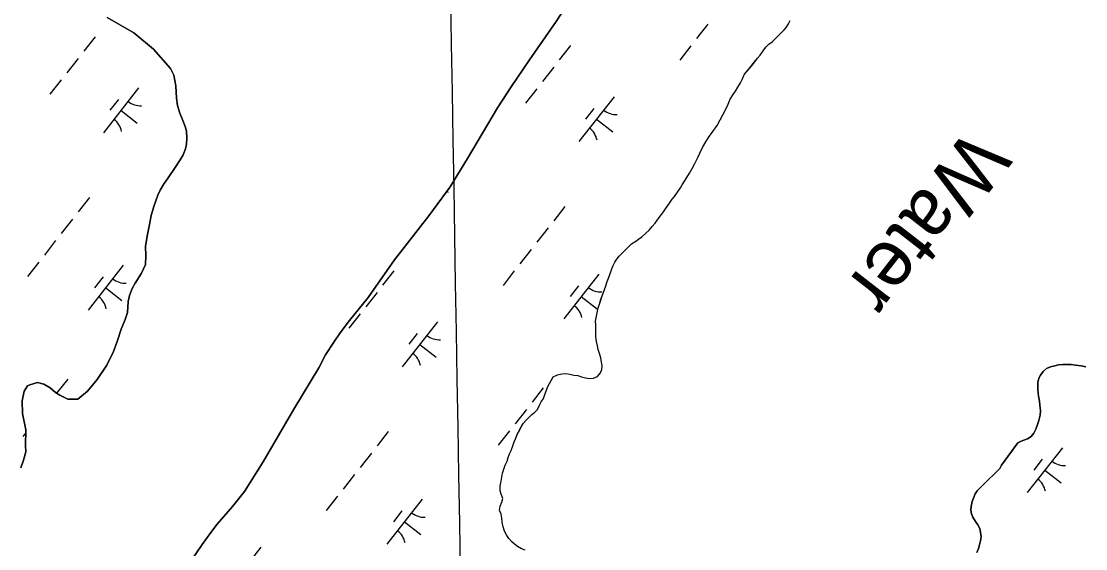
# Model space of a CAD drawing. Extents: x 3896831 to 3918110, y 171006 to 193349.
# Drawn here: x 3909330 to 3910262, y 178046 to 178509 of the extents above; entities that cross this region are included whole.
import ezdxf

# ---------------------------------------------------------------- set-up
doc = ezdxf.new("R2010")
doc.units = 0
for name, color, linetype in [('V-GRID-MAJR', 7, 'Continuous'), ('V-RIVR-IDEN', 7, 'Continuous'), ('V-TOPO-SHOR', 7, 'Continuous'), ('V-WETL-SWMP', 7, 'Continuous')]:
    doc.layers.add(name, color=color, linetype=linetype)

msp = doc.modelspace()

# ---------------------------------------------------------------- linework, layer by layer
at = {"layer": 'V-GRID-MAJR'}
msp.add_spline([(3909752.76, 175802.03), (3909660.52, 181175.42), (3909556.5, 187235.56), (3909500.71, 190486.24)], degree=3, dxfattribs=at)
at = {"layer": 'V-TOPO-SHOR'}
for points in [[(3909488.26, 178050.08), (3909495.83, 178060.47), (3909501.33, 178067.84), (3909514.75, 178083.45), (3909525.17, 178096.46), (3909541.48, 178122.43), (3909568.51, 178168.75), (3909590.25, 178205.02), (3909596.09, 178216.39), (3909603.41, 178227.46), (3909608.93, 178235.75), (3909617.17, 178246.4), (3909633.49, 178266.63), (3909656.76, 178299.8), (3909686.69, 178338.18), (3909705.53, 178363.69), (3909720.48, 178388.62), (3909746.94, 178433.08), (3909758.81, 178451.4), (3909774.94, 178475.11), (3909798.36, 178508.68), (3909820.87, 178543.87)], [(3909424.36, 178268.46), (3909426.89, 178274.41), (3909429.39, 178279.3), (3909435.04, 178287.85), (3909438.4, 178295.52), (3909438.83, 178303.24), (3909438.61, 178311.65), (3909440.3, 178322.02), (3909442.24, 178331.99), (3909443.45, 178338.63), (3909445.75, 178346.46), (3909449.43, 178356.38), (3909451.25, 178360.75), (3909454.16, 178365.62), (3909458.42, 178371.54), (3909464.48, 178380.75), (3909469.02, 178387.32), (3909471.65, 178391.67), (3909473.63, 178396.97), (3909474.39, 178401.22), (3909474.76, 178406.41), (3909474.49, 178412.42), (3909473.38, 178416.71), (3909471.35, 178421.83), (3909468.55, 178428.29), (3909466.56, 178435.14), (3909465.63, 178441.56), (3909465.06, 178452.24), (3909463.25, 178461.75), (3909460.31, 178467.55), (3909445.59, 178484.54), (3909428.28, 178498.65), (3909404.95, 178512.21)], [(3909887.17, 178334.86), (3909889.5, 178338.01), (3909891.7, 178341.04), (3909894.04, 178344.45), (3909896.93, 178348.52), (3909899.95, 178352.86), (3909901.87, 178355.35), (3909904.62, 178359.16), (3909907.09, 178362.71), (3909908.75, 178365.47), (3909910.69, 178368.77), (3909912.89, 178371.92), (3909915.23, 178375.74), (3909917.58, 178379.82), (3909919.67, 178384.04), (3909922.32, 178389.45), (3909924.27, 178393.28), (3909926.64, 178398.3), (3909929.41, 178403.17), (3909931.89, 178406.85), (3909939.31, 178417.36), (3909946.95, 178431.73), (3909948.91, 178436.23), (3909950.87, 178440.58), (3909953.35, 178444.53), (3909955.28, 178447.56), (3909957.48, 178450.98), (3909959.7, 178454.93), (3909961.36, 178457.83), (3909963.2, 178462.59), (3909966.48, 178466.39), (3909969.34, 178469.66), (3909972.22, 178473.2), (3909974.82, 178476.48), (3909977.01, 178479.23), (3909980.31, 178483.96), (3909982.37, 178486.59), (3909984.55, 178488.81), (3909987.52, 178490.74), (3909990.25, 178493.49), (3909992.83, 178496.1), (3909995.43, 178498.84), (3909998.01, 178501.45), (3910000.06, 178503.68), (3910001.99, 178506.57), (3910003.38, 178509.47)], [(3909764.46, 178048.26), (3909761.71, 178050.32), (3909759.35, 178052.37), (3909756.75, 178055.35), (3909754.94, 178058.06), (3909753.15, 178061.83), (3909751.89, 178065.46), (3909751.05, 178069.61), (3909750.72, 178073.08), (3909750, 178076.7), (3909748.74, 178080.19), (3909749.34, 178083.51), (3909750.75, 178087.21), (3909751.49, 178090.4), (3909750.23, 178094.29), (3909749.36, 178097.24), (3909749.31, 178101.11), (3909750.08, 178105.63), (3909750.68, 178109.08), (3909751.42, 178112.66), (3909752.56, 178116.24), (3909753.7, 178119.55), (3909755.24, 178122.98), (3909756.25, 178126.43), (3909757.51, 178129.6), (3909758.77, 178132.51), (3909760.33, 178136.61), (3909761.6, 178140.05), (3909762.87, 178143.36), (3909764.27, 178146.53), (3909766.08, 178149.95), (3909767.74, 178153.12), (3909769.81, 178156.41), (3909772, 178159.03), (3909774.59, 178161.77), (3909776.9, 178163.99), (3909779.48, 178166.07), (3909781.8, 178168.56), (3909783.74, 178172.12), (3909785.14, 178175.02), (3909787.07, 178178.18), (3909788.47, 178181.48), (3909789.89, 178185.32), (3909790.89, 178188.5), (3909792.41, 178191.13), (3909793.93, 178193.77), (3909795.73, 178196.93), (3909799.51, 178198.85), (3909803.12, 178199.57), (3909806.46, 178200.04), (3909810.31, 178199.29), (3909813.9, 178198.55), (3909817.36, 178198.21), (3909820.4, 178197.21), (3909823.98, 178196.07), (3909827.57, 178195.73), (3909831.04, 178195.92), (3909834.54, 178197.31), (3909837, 178200.46), (3909838.27, 178203.36), (3909838.47, 178206.83), (3909838.14, 178209.9), (3909837.42, 178213.78), (3909836.17, 178217.54), (3909835.04, 178221.03), (3909834.44, 178224.24), (3909833.72, 178227.99), (3909833.14, 178232.01), (3909832.94, 178235.48), (3909833.01, 178238.54), (3909832.96, 178242.54), (3909832.9, 178246.01), (3909833.52, 178250.13), (3909834.12, 178253.18), (3909835.15, 178257.7), (3909836.14, 178260.74), (3909837.29, 178264.32), (3909838.42, 178267.36), (3909839.55, 178270.4), (3909840.68, 178273.58), (3909841.81, 178276.89), (3909843.09, 178280.59), (3909844.09, 178283.51), (3909845.36, 178286.95), (3909846.36, 178290.12), (3909848.04, 178294.09), (3909849.59, 178297.66), (3909851.38, 178300.29), (3909853.56, 178302.77), (3909856.15, 178305.52), (3909858.47, 178308), (3909861.47, 178310.87), (3909864.32, 178313.61), (3909867.97, 178315.93), (3909870.41, 178317.75), (3909873.26, 178319.96), (3909876.79, 178323.08), (3909879.77, 178325.55), (3909882.38, 178328.83), (3909884.97, 178331.71), (3909887.17, 178334.86)], [(3909329.38, 178117.18), (3909331.53, 178124.07), (3909333.55, 178131.23), (3909333.39, 178136.57), (3909333.56, 178150.58), (3909330.79, 178164.77), (3909330.49, 178176.12), (3909332.13, 178184.36), (3909335.04, 178189.23), (3909337.19, 178190.12), (3909343.77, 178191.98), (3909349.47, 178190.53), (3909355.01, 178187.34), (3909359.59, 178183.24), (3909363.55, 178180.89), (3909370.41, 178177.41), (3909379.09, 178177.63), (3909387.64, 178184.52), (3909396.26, 178194.75), (3909404.53, 178207.38), (3909410.38, 178219.4), (3909413.64, 178228.13), (3909417.07, 178239), (3909420.72, 178247.46), (3909422.84, 178253.42), (3909423.31, 178263.01), (3909424.36, 178268.46)], [(3910221.13, 178196.03), (3910222.7, 178198.66), (3910225.06, 178201.73), (3910227.95, 178204.42), (3910231.44, 178205.95), (3910235.06, 178206.86), (3910238.41, 178207.45), (3910242.15, 178207.77), (3910245.48, 178207.84), (3910249.35, 178207.89), (3910253.34, 178207.4), (3910258.13, 178206.64), (3910262.38, 178205.88)], [(3910166.89, 178043.04), (3910168.29, 178046.48), (3910169.3, 178049.79), (3910170.04, 178053.37), (3910170.51, 178056.83), (3910170.2, 178060.7), (3910169.33, 178063.92), (3910167.8, 178067.18), (3910165.57, 178070.32), (3910163.28, 178074.13), (3910162.19, 178077.06), (3910161.49, 178080.22), (3910161.77, 178083.47), (3910162.74, 178087.79), (3910163.92, 178090.6), (3910165.47, 178094.43), (3910167.12, 178097.06), (3910169.98, 178100.07), (3910173.66, 178103.59), (3910175.97, 178105.81), (3910178.02, 178108.03), (3910181.01, 178110.9), (3910184.14, 178113.77), (3910186.87, 178116.78), (3910188.53, 178119.68), (3910202.68, 178139.11), (3910205.77, 178140.51), (3910211.15, 178142.67), (3910214.4, 178144.86), (3910216.72, 178147.75), (3910218.53, 178151.04), (3910219.8, 178154.48), (3910221.23, 178158.86), (3910222.25, 178163.37), (3910222.48, 178167.63), (3910222.18, 178172.33), (3910221.63, 178175.73), (3910220.82, 178180.22), (3910220.17, 178186.02), (3910220.25, 178192.18), (3910221.13, 178196.03)], [(3909319.59, 177836.97), (3909330.11, 177847.7), (3909339.77, 177856.31), (3909347.55, 177864.16), (3909357.1, 177873.31), (3909362.55, 177878.67), (3909370.07, 177886.67), (3909376.38, 177894.68), (3909381.91, 177903.65), (3909387.01, 177910.75), (3909427.16, 177964.94), (3909463.83, 178012.93), (3909478.33, 178035.46), (3909488.26, 178050.08)], [(3909771.06, 178044.92), (3909768.02, 178046.32), (3909764.46, 178048.26)]]:
    msp.add_lwpolyline(points, dxfattribs=at)
at = {"layer": 'V-WETL-SWMP'}
for p, q in [((3909820.87, 178543.87), (3909798.36, 178508.68)), ((3909404.95, 178512.21), (3909428.28, 178498.65)), ((3909798.36, 178508.68), (3909774.94, 178475.11)), ((3910001.99, 178506.57), (3910003.38, 178509.47)), ((3909428.28, 178498.65), (3909445.59, 178484.54)), ((3909931.2, 178506.31), (3909921.33, 178493.72)), ((3909992.83, 178496.1), (3909995.43, 178498.84)), ((3909995.43, 178498.84), (3909998.01, 178501.46)), ((3909998.01, 178501.46), (3910000.06, 178503.68)), ((3910000.06, 178503.68), (3910001.99, 178506.57)), ((3909394.29, 178495.25), (3909384.42, 178482.66)), ((3909982.37, 178486.58), (3909984.55, 178488.81)), ((3909984.55, 178488.81), (3909987.52, 178490.74)), ((3909987.52, 178490.74), (3909990.25, 178493.48)), ((3909990.25, 178493.48), (3909992.83, 178496.1)), ((3909445.59, 178484.54), (3909460.31, 178467.55)), ((3909810.94, 178487.55), (3909801.07, 178474.96)), ((3909916.4, 178487.42), (3909906.53, 178474.83)), ((3909977.01, 178479.23), (3909980.31, 178483.96)), ((3909980.31, 178483.96), (3909982.37, 178486.58)), ((3909379.49, 178476.36), (3909369.62, 178463.77)), ((3909774.94, 178475.11), (3909758.81, 178451.4)), ((3909972.74, 178474.49), (3909965.52, 178465.29)), ((3909969.34, 178469.66), (3909972.22, 178473.2)), ((3909972.22, 178473.2), (3909974.82, 178476.48)), ((3909974.82, 178476.48), (3909977.01, 178479.23)), ((3909460.31, 178467.55), (3909463.25, 178461.75)), ((3909463.25, 178461.75), (3909465.06, 178452.24)), ((3909796.13, 178468.66), (3909786.26, 178456.07)), ((3909961.36, 178457.83), (3909963.2, 178462.59)), ((3909963.2, 178462.59), (3909966.48, 178466.39)), ((3909966.48, 178466.39), (3909969.34, 178469.66)), ((3909364.68, 178457.48), (3909354.81, 178444.88)), ((3909465.06, 178452.24), (3909465.63, 178441.56)), ((3909758.81, 178451.4), (3909746.94, 178433.08)), ((3909957.48, 178450.98), (3909959.7, 178454.93)), ((3909959.7, 178454.93), (3909961.36, 178457.83)), ((3909432.5, 178450.44), (3909401.66, 178411.09)), ((3909781.33, 178449.78), (3909771.46, 178437.18)), ((3909849.14, 178442.74), (3909818.3, 178403.39)), ((3909950.86, 178440.58), (3909953.35, 178444.53)), ((3909953.35, 178444.53), (3909955.28, 178447.56)), ((3909955.28, 178447.56), (3909957.48, 178450.98)), ((3909414.71, 178440.24), (3909407.3, 178430.8)), ((3909465.63, 178441.56), (3909466.56, 178435.14)), ((3909466.56, 178435.14), (3909468.55, 178428.29)), ((3909746.94, 178433.08), (3909720.48, 178388.62)), ((3909946.95, 178431.73), (3909948.91, 178436.23)), ((3909948.91, 178436.23), (3909950.86, 178440.58)), ((3909417.08, 178430.76), (3909431.25, 178419.66)), ((3909468.55, 178428.29), (3909471.35, 178421.83)), ((3909831.35, 178432.54), (3909823.95, 178423.1)), ((3909939.31, 178417.36), (3909946.95, 178431.73)), ((3909471.35, 178421.83), (3909473.38, 178416.71)), ((3909473.38, 178416.71), (3909474.49, 178412.42)), ((3909833.72, 178423.06), (3909847.89, 178411.96)), ((3909931.89, 178406.85), (3909939.31, 178417.36)), ((3909474.76, 178406.41), (3909474.39, 178401.22)), ((3909474.49, 178412.42), (3909474.76, 178406.41)), ((3909929.41, 178403.17), (3909931.89, 178406.85)), ((3909473.63, 178396.96), (3909471.65, 178391.67)), ((3909474.39, 178401.22), (3909473.63, 178396.96)), ((3909924.27, 178393.28), (3909926.64, 178398.3)), ((3909926.64, 178398.3), (3909929.41, 178403.17)), ((3909469.02, 178387.32), (3909464.48, 178380.75)), ((3909471.65, 178391.67), (3909469.02, 178387.32)), ((3909720.48, 178388.62), (3909705.53, 178363.69)), ((3909919.67, 178384.04), (3909922.32, 178389.45)), ((3909922.32, 178389.45), (3909924.27, 178393.28)), ((3909464.48, 178380.75), (3909458.42, 178371.54)), ((3909915.23, 178375.74), (3909917.58, 178379.82)), ((3909917.58, 178379.82), (3909919.67, 178384.04)), ((3909458.42, 178371.54), (3909454.16, 178365.62)), ((3909908.75, 178365.47), (3909910.69, 178368.77)), ((3909910.69, 178368.77), (3909912.88, 178371.92)), ((3909912.88, 178371.92), (3909915.23, 178375.74)), ((3909451.25, 178360.75), (3909449.43, 178356.39)), ((3909454.16, 178365.62), (3909451.25, 178360.75)), ((3909705.53, 178363.69), (3909686.69, 178338.18)), ((3909702.61, 178359.74), (3909703.55, 178359)), ((3909901.87, 178355.35), (3909904.62, 178359.16)), ((3909904.62, 178359.16), (3909907.09, 178362.71)), ((3909907.09, 178362.71), (3909908.75, 178365.47)), ((3909389.37, 178354.28), (3909379.5, 178341.68)), ((3909449.43, 178356.39), (3909445.75, 178346.46)), ((3909896.93, 178348.52), (3909899.95, 178352.86)), ((3909899.95, 178352.86), (3909901.87, 178355.35)), ((3909445.75, 178346.46), (3909443.45, 178338.63)), ((3909806.01, 178346.58), (3909796.14, 178333.98)), ((3909889.5, 178338.01), (3909891.7, 178341.03)), ((3909891.7, 178341.03), (3909894.04, 178344.45)), ((3909894.04, 178344.45), (3909896.93, 178348.52)), ((3909374.56, 178335.39), (3909364.69, 178322.79)), ((3909442.24, 178331.99), (3909440.3, 178322.02)), ((3909443.45, 178338.63), (3909442.24, 178331.99)), ((3909686.69, 178338.18), (3909656.76, 178299.8)), ((3909882.38, 178328.83), (3909884.97, 178331.71)), ((3909884.97, 178331.71), (3909887.17, 178334.86)), ((3909887.17, 178334.86), (3909889.5, 178338.01)), ((3909440.3, 178322.02), (3909438.61, 178311.65)), ((3909791.2, 178327.69), (3909781.33, 178315.09)), ((3909873.26, 178319.96), (3909876.79, 178323.08)), ((3909876.79, 178323.08), (3909879.77, 178325.55)), ((3909879.77, 178325.55), (3909882.38, 178328.83)), ((3909359.76, 178316.5), (3909349.89, 178303.9)), ((3909438.61, 178311.65), (3909438.83, 178303.24)), ((3909858.47, 178308), (3909864.32, 178313.61)), ((3909864.32, 178313.61), (3909867.97, 178315.93)), ((3909867.97, 178315.93), (3909870.41, 178317.75)), ((3909870.41, 178317.75), (3909873.26, 178319.96)), ((3909438.83, 178303.24), (3909438.4, 178295.51)), ((3909776.4, 178308.8), (3909766.53, 178296.2)), ((3909851.38, 178300.29), (3909853.56, 178302.77)), ((3909853.56, 178302.77), (3909856.15, 178305.52)), ((3909856.15, 178305.52), (3909858.47, 178308)), ((3909344.95, 178297.61), (3909335.08, 178285.01)), ((3909419.08, 178294.87), (3909388.24, 178255.52)), ((3909438.4, 178295.51), (3909435.04, 178287.85)), ((3909656.76, 178299.8), (3909633.49, 178266.63)), ((3909846.36, 178290.12), (3909848.04, 178294.09)), ((3909848.04, 178294.09), (3909849.59, 178297.66)), ((3909849.59, 178297.66), (3909851.38, 178300.29)), ((3909401.29, 178284.68), (3909393.89, 178275.23)), ((3909435.04, 178287.85), (3909429.39, 178279.3)), ((3909656.13, 178290.04), (3909646.26, 178277.44)), ((3909761.59, 178289.91), (3909751.72, 178277.31)), ((3909835.73, 178287.17), (3909804.88, 178247.82)), ((3909844.09, 178283.51), (3909845.36, 178286.95)), ((3909845.36, 178286.95), (3909846.36, 178290.12)), ((3909403.66, 178275.19), (3909417.83, 178264.09)), ((3909426.89, 178274.41), (3909424.36, 178268.46)), ((3909429.39, 178279.3), (3909426.89, 178274.41)), ((3909817.93, 178276.98), (3909810.53, 178267.53)), ((3909840.68, 178273.58), (3909841.82, 178276.89)), ((3909841.82, 178276.89), (3909843.09, 178280.59)), ((3909843.09, 178280.59), (3909844.09, 178283.51)), ((3909424.36, 178268.46), (3909423.31, 178263.01)), ((3909633.49, 178266.63), (3909617.17, 178246.4)), ((3909641.33, 178271.15), (3909631.46, 178258.55)), ((3909820.31, 178267.49), (3909834.47, 178256.39)), ((3909837.28, 178264.32), (3909839.55, 178270.4)), ((3909839.55, 178270.4), (3909840.68, 178273.58)), ((3909423.31, 178263.01), (3909422.84, 178253.42)), ((3909834.12, 178253.18), (3909835.15, 178257.7)), ((3909835.15, 178257.7), (3909836.14, 178260.74)), ((3909836.14, 178260.74), (3909837.28, 178264.32)), ((3909420.71, 178247.46), (3909417.07, 178239)), ((3909422.84, 178253.42), (3909420.71, 178247.46)), ((3909617.17, 178246.4), (3909608.93, 178235.75)), ((3909626.52, 178252.26), (3909616.65, 178239.67)), ((3909832.9, 178246.01), (3909833.52, 178250.13)), ((3909833.52, 178250.13), (3909834.12, 178253.18)), ((3909417.07, 178239), (3909413.64, 178228.13)), ((3909694.34, 178245.22), (3909663.49, 178205.87)), ((3909832.96, 178242.54), (3909832.9, 178246.01)), ((3909832.94, 178235.48), (3909833.01, 178238.54)), ((3909833.01, 178238.54), (3909832.96, 178242.54)), ((3909413.64, 178228.13), (3909410.38, 178219.39)), ((3909608.93, 178235.75), (3909603.41, 178227.46)), ((3909676.54, 178235.03), (3909669.14, 178225.58)), ((3909833.14, 178232.01), (3909832.94, 178235.48)), ((3909833.72, 178227.99), (3909833.14, 178232.01)), ((3909834.44, 178224.24), (3909833.72, 178227.99)), ((3909410.38, 178219.39), (3909404.53, 178207.38)), ((3909603.41, 178227.46), (3909596.09, 178216.39)), ((3909678.92, 178225.55), (3909693.08, 178214.44)), ((3909835.04, 178221.03), (3909834.44, 178224.24)), ((3909836.17, 178217.54), (3909835.04, 178221.03)), ((3909596.09, 178216.39), (3909590.24, 178205.02)), ((3909837.42, 178213.78), (3909836.17, 178217.54)), ((3909838.14, 178209.9), (3909837.42, 178213.78)), ((3909838.47, 178206.83), (3909838.14, 178209.9)), ((3909404.53, 178207.38), (3909396.26, 178194.74)), ((3909590.24, 178205.02), (3909568.51, 178168.75)), ((3909803.12, 178199.57), (3909806.46, 178200.03)), ((3909806.46, 178200.03), (3909810.31, 178199.29)), ((3909834.54, 178197.31), (3909837, 178200.46)), ((3909837, 178200.46), (3909838.27, 178203.36)), ((3909838.27, 178203.36), (3909838.47, 178206.83)), ((3910225.06, 178201.73), (3910222.7, 178198.66)), ((3910227.95, 178204.42), (3910225.06, 178201.73)), ((3910231.44, 178205.95), (3910227.95, 178204.42)), ((3910235.06, 178206.86), (3910231.44, 178205.95)), ((3910238.41, 178207.45), (3910235.06, 178206.86)), ((3910242.15, 178207.77), (3910238.41, 178207.45)), ((3910245.48, 178207.84), (3910242.15, 178207.77)), ((3910249.35, 178207.89), (3910245.48, 178207.84)), ((3910253.34, 178207.4), (3910249.35, 178207.89)), ((3910258.13, 178206.64), (3910253.34, 178207.4)), ((3910262.38, 178205.88), (3910258.13, 178206.64)), ((3909343.77, 178191.98), (3909337.19, 178190.12)), ((3909349.47, 178190.53), (3909343.77, 178191.98)), ((3909355.01, 178187.34), (3909349.47, 178190.53)), ((3909370.41, 178195.13), (3909360.62, 178182.64)), ((3909396.26, 178194.74), (3909387.64, 178184.52)), ((3909790.89, 178188.5), (3909793.93, 178193.77)), ((3909793.93, 178193.77), (3909795.73, 178196.93)), ((3909795.73, 178196.93), (3909799.5, 178198.85)), ((3909799.5, 178198.85), (3909803.12, 178199.57)), ((3909810.31, 178199.29), (3909813.9, 178198.55)), ((3909813.9, 178198.55), (3909817.36, 178198.21)), ((3909817.36, 178198.21), (3909820.4, 178197.21)), ((3909820.4, 178197.21), (3909823.98, 178196.07)), ((3909823.98, 178196.07), (3909827.57, 178195.72)), ((3909827.57, 178195.72), (3909831.04, 178195.92)), ((3909831.04, 178195.92), (3909834.54, 178197.31)), ((3910220.25, 178192.18), (3910220.17, 178186.02)), ((3910221.13, 178196.03), (3910220.25, 178192.18)), ((3910222.7, 178198.66), (3910221.13, 178196.03)), ((3909332.13, 178184.36), (3909330.49, 178176.12)), ((3909335.04, 178189.23), (3909332.13, 178184.36)), ((3909337.19, 178190.12), (3909335.04, 178189.23)), ((3909359.59, 178183.24), (3909355.01, 178187.34)), ((3909363.55, 178180.89), (3909359.59, 178183.24)), ((3909387.64, 178184.52), (3909379.09, 178177.63)), ((3909787.05, 178187.43), (3909777.18, 178174.84)), ((3909787.07, 178178.18), (3909788.47, 178181.48)), ((3909788.47, 178181.48), (3909789.89, 178185.32)), ((3909789.89, 178185.32), (3909790.89, 178188.5)), ((3910220.17, 178186.02), (3910220.82, 178180.22)), ((3909330.49, 178176.12), (3909330.79, 178164.77)), ((3909370.41, 178177.41), (3909363.55, 178180.89)), ((3909379.09, 178177.63), (3909370.41, 178177.41)), ((3909781.8, 178168.56), (3909783.74, 178172.11)), ((3909783.74, 178172.11), (3909785.14, 178175.02)), ((3909785.14, 178175.02), (3909787.07, 178178.18)), ((3910220.82, 178180.22), (3910221.63, 178175.73)), ((3910221.63, 178175.73), (3910222.18, 178172.33)), ((3910222.18, 178172.33), (3910222.48, 178167.63)), ((3909330.79, 178164.77), (3909333.56, 178150.57)), ((3909568.51, 178168.75), (3909541.48, 178122.43)), ((3909772.24, 178168.54), (3909762.37, 178155.95)), ((3909774.59, 178161.77), (3909776.9, 178163.99)), ((3909776.9, 178163.99), (3909779.48, 178166.07)), ((3909779.48, 178166.07), (3909781.8, 178168.56)), ((3910222.25, 178163.37), (3910221.23, 178158.85)), ((3910222.48, 178167.63), (3910222.25, 178163.37)), ((3909764.27, 178146.53), (3909767.74, 178153.12)), ((3909767.74, 178153.12), (3909769.81, 178156.41)), ((3909769.81, 178156.41), (3909772, 178159.03)), ((3909772, 178159.03), (3909774.59, 178161.77)), ((3910219.8, 178154.48), (3910218.53, 178151.04)), ((3910221.23, 178158.85), (3910219.8, 178154.48)), ((3909333.53, 178148.07), (3909330.93, 178144.76)), ((3909333.56, 178150.57), (3909333.39, 178136.57)), ((3909651.2, 178149.06), (3909641.33, 178136.46)), ((3909757.44, 178149.65), (3909747.57, 178137.06)), ((3909762.87, 178143.36), (3909764.27, 178146.53)), ((3910214.4, 178144.86), (3910211.15, 178142.67)), ((3910216.72, 178147.75), (3910214.4, 178144.86)), ((3910218.53, 178151.04), (3910216.72, 178147.75)), ((3909333.39, 178136.57), (3909333.55, 178131.23)), ((3909758.77, 178132.51), (3909760.33, 178136.61)), ((3909760.33, 178136.61), (3909761.6, 178140.05)), ((3909761.6, 178140.05), (3909762.87, 178143.36)), ((3910202.68, 178139.11), (3910188.53, 178119.68)), ((3910205.77, 178140.51), (3910202.68, 178139.11)), ((3910211.15, 178142.67), (3910205.77, 178140.51)), ((3910241.9, 178134.91), (3910211.06, 178095.56)), ((3909333.55, 178131.23), (3909331.53, 178124.07)), ((3909636.4, 178130.17), (3909626.53, 178117.58)), ((3909755.24, 178122.98), (3909756.25, 178126.43)), ((3909756.25, 178126.43), (3909757.51, 178129.6)), ((3909757.51, 178129.6), (3909758.77, 178132.51)), ((3909331.53, 178124.07), (3909329.38, 178117.18)), ((3909541.48, 178122.43), (3909525.17, 178096.46)), ((3909751.42, 178112.67), (3909752.56, 178116.24)), ((3909752.56, 178116.24), (3909753.7, 178119.55)), ((3909753.7, 178119.55), (3909755.24, 178122.98)), ((3910186.87, 178116.78), (3910184.14, 178113.77)), ((3910188.53, 178119.68), (3910186.87, 178116.78)), ((3910224.11, 178124.72), (3910216.7, 178115.27)), ((3909621.59, 178111.28), (3909611.72, 178098.69)), ((3909750.07, 178105.63), (3909750.68, 178109.08)), ((3909750.68, 178109.08), (3909751.42, 178112.67)), ((3910178.02, 178108.03), (3910175.97, 178105.81)), ((3910181.01, 178110.9), (3910178.02, 178108.03)), ((3910184.14, 178113.77), (3910181.01, 178110.9)), ((3910226.48, 178115.24), (3910240.64, 178104.13)), ((3909749.31, 178101.11), (3909750.07, 178105.63)), ((3909749.36, 178097.24), (3909749.31, 178101.11)), ((3909750.23, 178094.29), (3909749.36, 178097.24)), ((3910167.12, 178097.06), (3910165.47, 178094.43)), ((3910169.98, 178100.07), (3910167.12, 178097.06)), ((3910175.97, 178105.81), (3910169.98, 178100.07)), ((3909525.17, 178096.46), (3909514.75, 178083.45)), ((3909606.79, 178092.39), (3909596.92, 178079.8)), ((3909680.92, 178089.65), (3909650.08, 178050.3)), ((3909751.49, 178090.4), (3909750.23, 178094.29)), ((3909750.75, 178087.21), (3909751.49, 178090.4)), ((3910162.74, 178087.79), (3910161.77, 178083.47)), ((3910163.92, 178090.6), (3910162.74, 178087.79)), ((3910165.47, 178094.43), (3910163.92, 178090.6)), ((3909514.75, 178083.45), (3909501.33, 178067.84)), ((3909663.13, 178079.46), (3909655.73, 178070.01)), ((3909748.74, 178080.19), (3909749.34, 178083.51)), ((3909750, 178076.7), (3909748.74, 178080.19)), ((3909749.34, 178083.51), (3909750.75, 178087.21)), ((3910161.77, 178083.47), (3910161.49, 178080.22)), ((3910161.49, 178080.22), (3910162.19, 178077.06)), ((3909665.5, 178069.98), (3909679.67, 178058.87)), ((3909750.72, 178073.08), (3909750, 178076.7)), ((3909751.05, 178069.61), (3909750.72, 178073.08)), ((3909751.89, 178065.46), (3909751.05, 178069.61)), ((3910162.19, 178077.06), (3910163.28, 178074.13)), ((3910163.28, 178074.13), (3910165.57, 178070.32)), ((3910165.57, 178070.32), (3910167.8, 178067.18)), ((3909495.83, 178060.47), (3909488.26, 178050.08)), ((3909501.33, 178067.84), (3909495.83, 178060.47)), ((3909753.15, 178061.83), (3909751.89, 178065.46)), ((3909754.94, 178058.06), (3909753.15, 178061.83)), ((3910167.8, 178067.18), (3910169.33, 178063.92)), ((3910169.33, 178063.92), (3910170.2, 178060.7)), ((3910170.2, 178060.7), (3910170.51, 178056.83)), ((3909756.75, 178055.35), (3909754.94, 178058.06)), ((3909759.35, 178052.37), (3909756.75, 178055.35)), ((3909761.71, 178050.32), (3909759.35, 178052.37)), ((3910170.04, 178053.37), (3910169.3, 178049.79)), ((3910170.51, 178056.83), (3910170.04, 178053.37)), ((3909488.26, 178050.08), (3909478.33, 178035.46)), ((3909539.53, 178047.7), (3909508.69, 178008.35)), ((3909764.46, 178048.26), (3909761.71, 178050.32)), ((3909768.02, 178046.32), (3909764.46, 178048.26)), ((3910168.29, 178046.48), (3910166.89, 178043.04)), ((3910169.3, 178049.79), (3910168.29, 178046.48))]:
    msp.add_line(p, q, dxfattribs=at)
for centre, start, end in [((3909434.3, 178452.36), 231.14028, 272.68394), ((3909850.95, 178444.66), 231.14028, 272.68394), ((3909400.23, 178408.88), 11.14028, 52.68394), ((3909816.87, 178401.18), 11.14028, 52.68394), ((3909420.89, 178296.79), 231.14028, 272.68394), ((3909837.53, 178289.09), 231.14028, 272.68394), ((3909386.81, 178253.31), 11.14028, 52.68394), ((3909803.45, 178245.61), 11.14028, 52.68394), ((3909696.14, 178247.14), 231.14028, 272.68394), ((3909662.06, 178203.66), 11.14028, 52.68394), ((3910243.7, 178136.83), 231.14028, 272.68394), ((3910209.62, 178093.35), 11.14028, 52.68394), ((3909682.73, 178091.57), 231.14028, 272.68394), ((3909648.65, 178048.09), 11.14028, 52.68394)]:
    msp.add_arc(centre, 17.62, start, end, dxfattribs=at)

# ---------------------------------------------------------------- texts
at = {"layer": 'V-RIVR-IDEN'}
msp.add_text('Water', height=50, rotation=232.08429, dxfattribs=at).set_placement((3910159.42, 178416.63))

doc.saveas('drawing.dxf')
